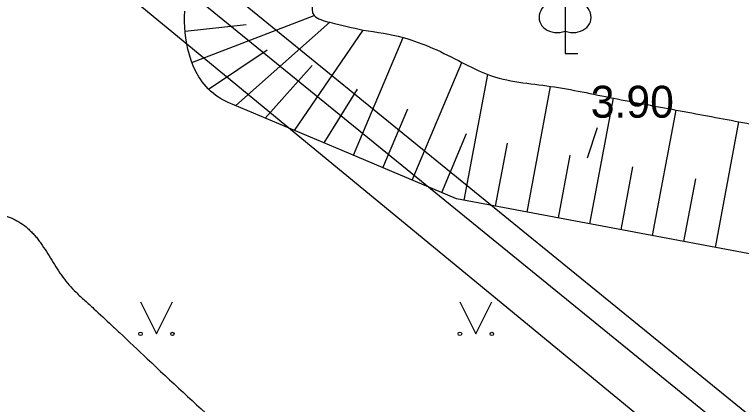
# Model space of a CAD drawing. Extents: x 519536 to 519949, y 326041 to 326519.
# Drawn here: x 519745.28 to 519756.66, y 326171.4 to 326177.5 of the extents above; entities that cross this region are included whole.
import ezdxf

# ---------------------------------------------------------------- set-up
doc = ezdxf.new("R2010")
doc.units = 0
for name, color, linetype in [('APGR_SARK_####_####_#', 7, 'Continuous'), ('RELJ_AATZ_####_TKST_#', 7, 'Continuous'), ('RELJ_HORZ_PAMT_####_#', 7, 'Continuous'), ('RELJ_NOGA_####_####_#', 7, 'Continuous'), ('RELJ_NOGL_####_####_#', 7, 'Continuous'), ('TERT_ELEM_####_####_#', 7, 'Continuous'), ('UDTK_VADP_UDEN_####_#', 7, 'Continuous')]:
    doc.layers.add(name, color=color, linetype=linetype)

msp = doc.modelspace()

# ---------------------------------------------------------------- linework, layer by layer
at = {"layer": 'APGR_SARK_####_####_#'}
msp.add_line((519731.697, 326190.43), (519783.534, 326147.79), dxfattribs=at)
at = {"layer": 'RELJ_HORZ_PAMT_####_#'}
msp.add_line((519754.25, 326175.254), (519754.405, 326175.73), dxfattribs=at)
for points in [[(519743.309, 326174.086), (519743.418, 326174.145), (519743.531, 326174.196), (519743.667, 326174.252), (519743.806, 326174.299), (519744.104, 326174.374), (519744.255, 326174.401), (519744.408, 326174.421), (519744.555, 326174.431), (519744.703, 326174.43), (519744.851, 326174.415), (519744.999, 326174.387), (519745.256, 326174.3), (519745.374, 326174.234), (519745.485, 326174.15), (519745.541, 326174.096), (519745.594, 326174.04), (519745.643, 326173.981), (519745.688, 326173.919), (519745.862, 326173.653), (519746.035, 326173.386), (519746.24, 326173.151), (519746.379, 326173.022), (519746.519, 326172.894), (519746.798, 326172.636), (519746.922, 326172.519)], [(519746.922, 326172.519), (519747.355, 326172.111), (519748.485, 326171.067), (519749.669, 326170.09), (519750.776, 326169.349)]]:
    msp.add_spline(points, degree=3, dxfattribs=at)
at = {"layer": 'RELJ_NOGA_####_####_#'}
for p, q in [((519748.054, 326176.749), (519749.969, 326177.484)), ((519747.949, 326177.237), (519748.905, 326177.342)), ((519748.741, 326176.072), (519750.215, 326177.377)), ((519749.662, 326175.684), (519750.737, 326177.254)), ((519750.584, 326175.295), (519751.361, 326177.138)), ((519748.316, 326176.328), (519749.234, 326176.946)), ((519749.202, 326175.878), (519749.939, 326176.7)), ((519751.505, 326174.906), (519752.282, 326176.749)), ((519752.318, 326174.592), (519752.688, 326176.558)), ((519753.301, 326174.407), (519753.671, 326176.373)), ((519750.123, 326175.489), (519750.645, 326176.33)), ((519754.284, 326174.223), (519754.653, 326176.188)), ((519751.044, 326175.101), (519751.433, 326176.022)), ((519755.267, 326174.038), (519755.636, 326176.003)), ((519756.25, 326173.853), (519756.619, 326175.819)), ((519751.966, 326174.712), (519752.354, 326175.634)), ((519752.81, 326174.5), (519752.995, 326175.482)), ((519753.793, 326174.315), (519753.977, 326175.298)), ((519754.775, 326174.13), (519754.96, 326175.113)), ((519755.758, 326173.945), (519755.943, 326174.928))]:
    msp.add_line(p, q, dxfattribs=at)
for points in [[(519752.196, 326174.615), (519750.408, 326175.369), (519748.621, 326176.123), (519748.568, 326176.147), (519748.518, 326176.174), (519748.471, 326176.202), (519748.427, 326176.233), (519748.385, 326176.265), (519748.347, 326176.298), (519748.31, 326176.333), (519748.276, 326176.37), (519748.244, 326176.407), (519748.215, 326176.446), (519748.187, 326176.485), (519748.161, 326176.525), (519748.115, 326176.608), (519748.076, 326176.693), (519748.042, 326176.779), (519748.015, 326176.866), (519747.992, 326176.954), (519747.974, 326177.041), (519747.961, 326177.129), (519747.951, 326177.215), (519747.944, 326177.3), (519747.941, 326177.384), (519747.94, 326177.467), (519747.942, 326177.548)], [(519752.196, 326174.615), (519750.408, 326175.369), (519748.621, 326176.123), (519748.568, 326176.147), (519748.518, 326176.174), (519748.471, 326176.202), (519748.427, 326176.233), (519748.385, 326176.265), (519748.347, 326176.298), (519748.31, 326176.333), (519748.276, 326176.37), (519748.244, 326176.407), (519748.215, 326176.446), (519748.187, 326176.485), (519748.161, 326176.525), (519748.115, 326176.608), (519748.076, 326176.693), (519748.042, 326176.779), (519748.015, 326176.866), (519747.992, 326176.954), (519747.974, 326177.041), (519747.961, 326177.129), (519747.951, 326177.215), (519747.944, 326177.3), (519747.941, 326177.384), (519747.94, 326177.467), (519747.942, 326177.548)], [(519752.196, 326174.615), (519750.408, 326175.369), (519748.621, 326176.123), (519748.568, 326176.147), (519748.518, 326176.174), (519748.471, 326176.202), (519748.427, 326176.233), (519748.385, 326176.265), (519748.347, 326176.298), (519748.31, 326176.333), (519748.276, 326176.37), (519748.244, 326176.407), (519748.215, 326176.446), (519748.187, 326176.485), (519748.161, 326176.525), (519748.115, 326176.608), (519748.076, 326176.693), (519748.042, 326176.779), (519748.015, 326176.866), (519747.992, 326176.954), (519747.974, 326177.041), (519747.961, 326177.129), (519747.951, 326177.215), (519747.944, 326177.3), (519747.941, 326177.384), (519747.94, 326177.467), (519747.942, 326177.548)], [(519752.196, 326174.615), (519750.408, 326175.369), (519748.621, 326176.123), (519748.568, 326176.147), (519748.518, 326176.174), (519748.471, 326176.202), (519748.427, 326176.233), (519748.385, 326176.265), (519748.347, 326176.298), (519748.31, 326176.333), (519748.276, 326176.37), (519748.244, 326176.407), (519748.215, 326176.446), (519748.187, 326176.485), (519748.161, 326176.525), (519748.115, 326176.608), (519748.076, 326176.693), (519748.042, 326176.779), (519748.015, 326176.866), (519747.992, 326176.954), (519747.974, 326177.041), (519747.961, 326177.129), (519747.951, 326177.215), (519747.944, 326177.3), (519747.941, 326177.384), (519747.94, 326177.467), (519747.942, 326177.548)], [(519752.196, 326174.615), (519750.408, 326175.369), (519748.621, 326176.123), (519748.568, 326176.147), (519748.518, 326176.174), (519748.471, 326176.202), (519748.427, 326176.233), (519748.385, 326176.265), (519748.347, 326176.298), (519748.31, 326176.333), (519748.276, 326176.37), (519748.244, 326176.407), (519748.215, 326176.446), (519748.187, 326176.485), (519748.161, 326176.525), (519748.115, 326176.608), (519748.076, 326176.693), (519748.042, 326176.779), (519748.015, 326176.866), (519747.992, 326176.954), (519747.974, 326177.041), (519747.961, 326177.129), (519747.951, 326177.215), (519747.944, 326177.3), (519747.941, 326177.384), (519747.94, 326177.467), (519747.942, 326177.548)], [(519752.196, 326174.615), (519750.408, 326175.369), (519748.621, 326176.123), (519748.568, 326176.147), (519748.518, 326176.174), (519748.471, 326176.202), (519748.427, 326176.233), (519748.385, 326176.265), (519748.347, 326176.298), (519748.31, 326176.333), (519748.276, 326176.37), (519748.244, 326176.407), (519748.215, 326176.446), (519748.187, 326176.485), (519748.161, 326176.525), (519748.115, 326176.608), (519748.076, 326176.693), (519748.042, 326176.779), (519748.015, 326176.866), (519747.992, 326176.954), (519747.974, 326177.041), (519747.961, 326177.129), (519747.951, 326177.215), (519747.944, 326177.3), (519747.941, 326177.384), (519747.94, 326177.467), (519747.942, 326177.548)], [(519752.196, 326174.615), (519750.408, 326175.369), (519748.621, 326176.123), (519748.568, 326176.147), (519748.518, 326176.174), (519748.471, 326176.202), (519748.427, 326176.233), (519748.385, 326176.265), (519748.347, 326176.298), (519748.31, 326176.333), (519748.276, 326176.37), (519748.244, 326176.407), (519748.215, 326176.446), (519748.187, 326176.485), (519748.161, 326176.525), (519748.115, 326176.608), (519748.076, 326176.693), (519748.042, 326176.779), (519748.015, 326176.866), (519747.992, 326176.954), (519747.974, 326177.041), (519747.961, 326177.129), (519747.951, 326177.215), (519747.944, 326177.3), (519747.941, 326177.384), (519747.94, 326177.467), (519747.942, 326177.548)], [(519752.196, 326174.615), (519750.408, 326175.369), (519748.621, 326176.123), (519748.568, 326176.147), (519748.518, 326176.174), (519748.471, 326176.202), (519748.427, 326176.233), (519748.385, 326176.265), (519748.347, 326176.298), (519748.31, 326176.333), (519748.276, 326176.37), (519748.244, 326176.407), (519748.215, 326176.446), (519748.187, 326176.485), (519748.161, 326176.525), (519748.115, 326176.608), (519748.076, 326176.693), (519748.042, 326176.779), (519748.015, 326176.866), (519747.992, 326176.954), (519747.974, 326177.041), (519747.961, 326177.129), (519747.951, 326177.215), (519747.944, 326177.3), (519747.941, 326177.384), (519747.94, 326177.467), (519747.942, 326177.548)], [(519752.196, 326174.615), (519750.408, 326175.369), (519748.621, 326176.123), (519748.568, 326176.147), (519748.518, 326176.174), (519748.471, 326176.202), (519748.427, 326176.233), (519748.385, 326176.265), (519748.347, 326176.298), (519748.31, 326176.333), (519748.276, 326176.37), (519748.244, 326176.407), (519748.215, 326176.446), (519748.187, 326176.485), (519748.161, 326176.525), (519748.115, 326176.608), (519748.076, 326176.693), (519748.042, 326176.779), (519748.015, 326176.866), (519747.992, 326176.954), (519747.974, 326177.041), (519747.961, 326177.129), (519747.951, 326177.215), (519747.944, 326177.3), (519747.941, 326177.384), (519747.94, 326177.467), (519747.942, 326177.548)], [(519752.196, 326174.615), (519750.408, 326175.369), (519748.621, 326176.123), (519748.568, 326176.147), (519748.518, 326176.174), (519748.471, 326176.202), (519748.427, 326176.233), (519748.385, 326176.265), (519748.347, 326176.298), (519748.31, 326176.333), (519748.276, 326176.37), (519748.244, 326176.407), (519748.215, 326176.446), (519748.187, 326176.485), (519748.161, 326176.525), (519748.115, 326176.608), (519748.076, 326176.693), (519748.042, 326176.779), (519748.015, 326176.866), (519747.992, 326176.954), (519747.974, 326177.041), (519747.961, 326177.129), (519747.951, 326177.215), (519747.944, 326177.3), (519747.941, 326177.384), (519747.94, 326177.467), (519747.942, 326177.548)], [(519752.196, 326174.615), (519750.408, 326175.369), (519748.621, 326176.123), (519748.568, 326176.147), (519748.518, 326176.174), (519748.471, 326176.202), (519748.427, 326176.233), (519748.385, 326176.265), (519748.347, 326176.298), (519748.31, 326176.333), (519748.276, 326176.37), (519748.244, 326176.407), (519748.215, 326176.446), (519748.187, 326176.485), (519748.161, 326176.525), (519748.115, 326176.608), (519748.076, 326176.693), (519748.042, 326176.779), (519748.015, 326176.866), (519747.992, 326176.954), (519747.974, 326177.041), (519747.961, 326177.129), (519747.951, 326177.215), (519747.944, 326177.3), (519747.941, 326177.384), (519747.94, 326177.467), (519747.942, 326177.548)], [(519752.196, 326174.615), (519750.408, 326175.369), (519748.621, 326176.123), (519748.568, 326176.147), (519748.518, 326176.174), (519748.471, 326176.202), (519748.427, 326176.233), (519748.385, 326176.265), (519748.347, 326176.298), (519748.31, 326176.333), (519748.276, 326176.37), (519748.244, 326176.407), (519748.215, 326176.446), (519748.187, 326176.485), (519748.161, 326176.525), (519748.115, 326176.608), (519748.076, 326176.693), (519748.042, 326176.779), (519748.015, 326176.866), (519747.992, 326176.954), (519747.974, 326177.041), (519747.961, 326177.129), (519747.951, 326177.215), (519747.944, 326177.3), (519747.941, 326177.384), (519747.94, 326177.467), (519747.942, 326177.548)], [(519764.868, 326173.38), (519761.511, 326172.864), (519752.196, 326174.615)], [(519764.868, 326173.38), (519761.511, 326172.864), (519752.196, 326174.615)], [(519764.868, 326173.38), (519761.511, 326172.864), (519752.196, 326174.615)], [(519764.868, 326173.38), (519761.511, 326172.864), (519752.196, 326174.615)], [(519764.868, 326173.38), (519761.511, 326172.864), (519752.196, 326174.615)], [(519764.868, 326173.38), (519761.511, 326172.864), (519752.196, 326174.615)], [(519764.868, 326173.38), (519761.511, 326172.864), (519752.196, 326174.615)], [(519764.868, 326173.38), (519761.511, 326172.864), (519752.196, 326174.615)], [(519764.868, 326173.38), (519761.511, 326172.864), (519752.196, 326174.615)], [(519764.868, 326173.38), (519761.511, 326172.864), (519752.196, 326174.615)], [(519764.868, 326173.38), (519761.511, 326172.864), (519752.196, 326174.615)], [(519764.868, 326173.38), (519761.511, 326172.864), (519752.196, 326174.615)]]:
    msp.add_lwpolyline(points, dxfattribs=at)
at = {"layer": 'RELJ_NOGL_####_####_#'}
msp.add_spline([(519750.737, 326177.254), (519750.215, 326177.377), (519749.969, 326177.484), (519750.048, 326177.953), (519750.261, 326178.326), (519750.676, 326178.661), (519751.369, 326179.175), (519752.072, 326179.621), (519752.69, 326179.926), (519753.234, 326180.089), (519753.479, 326180.102), (519753.717, 326179.972), (519754.546, 326179.412), (519755.374, 326178.852), (519756.203, 326178.292), (519757.672, 326177.735), (519758.639, 326177.481), (519759.607, 326177.228), (519760.574, 326176.974), (519761.541, 326176.72), (519762.508, 326176.467), (519763.476, 326176.213), (519764.443, 326175.959), (519765.393, 326175.925), (519765.768, 326175.898), (519766.265, 326175.777), (519766.935, 326175.588), (519767.042, 326175.305), (519766.305, 326175.453), (519765.567, 326175.211), (519764.648, 326175.432), (519763.823, 326175.243), (519762.834, 326175.091), (519761.846, 326174.939), (519761.533, 326174.895), (519760.55, 326175.08), (519759.567, 326175.264), (519758.585, 326175.449), (519757.602, 326175.634), (519756.619, 326175.819), (519755.636, 326176.003), (519754.653, 326176.188), (519753.671, 326176.373), (519752.688, 326176.558), (519752.282, 326176.749), (519751.361, 326177.138), (519750.737, 326177.254)], degree=3, dxfattribs=at)
at = {"layer": 'TERT_ELEM_####_####_#'}
for p, q in [((519753.897, 326177.237), (519753.897, 326176.89)), ((519753.897, 326176.89), (519754.097, 326176.89)), ((519747.25, 326173), (519747.5, 326172.5)), ((519747.5, 326172.5), (519747.75, 326173)), ((519752.25, 326173), (519752.5, 326172.5)), ((519752.5, 326172.5), (519752.75, 326173))]:
    msp.add_line(p, q, dxfattribs=at)
msp.add_lwpolyline([(519753.897, 326178.39), (519753.897, 326177.237)], dxfattribs=at)
for centre, radius in [((519747.25, 326172.5), 0.028), ((519747.75, 326172.5), 0.0263), ((519752.25, 326172.5), 0.028), ((519752.75, 326172.5), 0.0263)]:
    msp.add_circle(centre, radius, dxfattribs=at)
for centre, major_axis, start_param, end_param in [((519753.807, 326177.483), (0.307, 0.095), 1.570796, 4.752015), ((519753.987, 326177.483), (-0.307, 0.095), 1.531171, 4.712389)]:
    msp.add_ellipse(centre, major_axis=major_axis, ratio=0.814445, start_param=start_param, end_param=end_param, dxfattribs=at)
at = {"layer": 'UDTK_VADP_UDEN_####_#'}
for points in [[(519767.203, 326162.23), (519745.595, 326179.813)], [(519767.47, 326162.528), (519746.282, 326179.769)]]:
    msp.add_lwpolyline(points, dxfattribs=at)

# ---------------------------------------------------------------- texts
at = {"layer": 'RELJ_AATZ_####_TKST_#'}
msp.add_text('3.90', height=0.5, dxfattribs=at).set_placement((519754.299, 326175.883))

doc.saveas('drawing.dxf')
